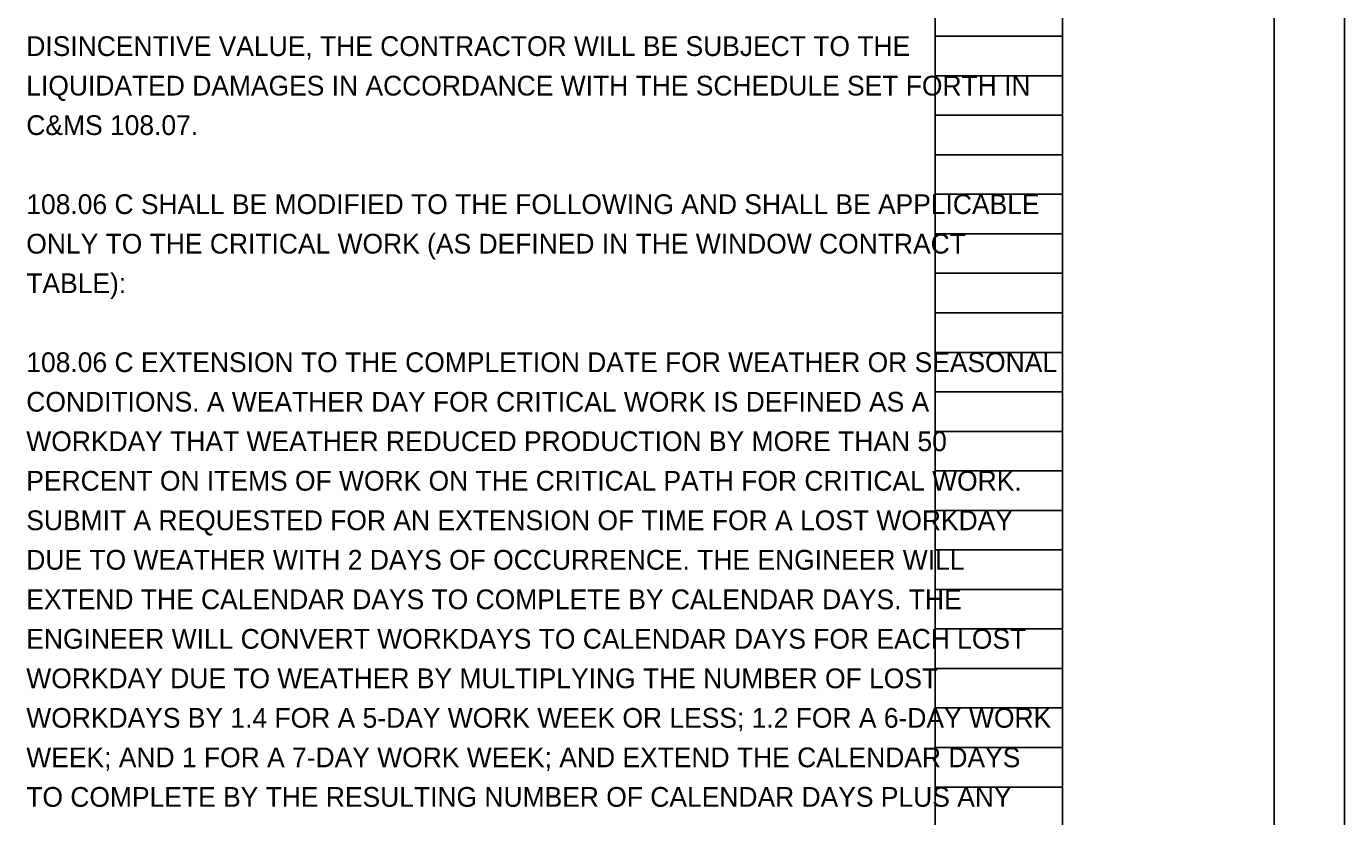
# Model space of a CAD drawing. Extents: x 0 to 84.3, y -13.4 to 22.
# Drawn here: x 24.66 to 34, y 5.53 to 11.13 of the extents above; entities that cross this region are included whole.
import ezdxf

# ---------------------------------------------------------------- set-up
doc = ezdxf.new("R2010")
doc.units = 0
for name, color, linetype in [('SH_Border', 7, 'Continuous'), ('SH_Cut_Line', 7, 'Continuous'), ('SH_Data', 7, 'Continuous'), ('SH_Text', 7, 'Continuous')]:
    doc.layers.add(name, color=color, linetype=linetype)

msp = doc.modelspace()

# ---------------------------------------------------------------- linework, layer by layer
at = {"layer": 'SH_Border'}
msp.add_line((32, 0.5), (32, 21.5), dxfattribs=at)
msp.add_lwpolyline([(1.5, 21.5), (33.5, 21.5), (33.5, 0.5), (1.5, 0.5)], close=True, dxfattribs=at)
at = {"layer": 'SH_Cut_Line'}
msp.add_lwpolyline([(0, 0), (34, 0), (34, 22), (0, 22)], close=True, dxfattribs=at)
at = {"layer": 'SH_Data'}
for p, q in [((31.1, 0.98), (31.1, 21.14)), ((32, 0.98), (32, 21.14)), ((31.1, 11.06), (32, 11.06)), ((31.1, 10.78), (32, 10.78)), ((31.1, 10.5), (32, 10.5)), ((31.1, 10.22), (32, 10.22)), ((31.1, 9.94), (32, 9.94)), ((31.1, 9.66), (32, 9.66)), ((31.1, 9.38), (32, 9.38)), ((31.1, 9.1), (32, 9.1)), ((31.1, 8.82), (32, 8.82)), ((31.1, 8.54), (32, 8.54)), ((31.1, 8.26), (32, 8.26)), ((31.1, 7.98), (32, 7.98)), ((31.1, 7.7), (32, 7.7)), ((31.1, 7.42), (32, 7.42)), ((31.1, 7.14), (32, 7.14)), ((31.1, 6.86), (32, 6.86)), ((31.1, 6.58), (32, 6.58)), ((31.1, 6.3), (32, 6.3)), ((31.1, 6.02), (32, 6.02)), ((31.1, 5.74), (32, 5.74))]:
    msp.add_line(p, q, dxfattribs=at)

# ---------------------------------------------------------------- texts
at = {"layer": 'SH_Text'}
for s, p in [('DISINCENTIVE VALUE, THE CONTRACTOR WILL BE SUBJECT TO THE ', (24.66, 10.92)), ('LIQUIDATED DAMAGES IN ACCORDANCE WITH THE SCHEDULE SET FORTH IN ', (24.66, 10.64)), ('C&MS 108.07.', (24.66, 10.36)), ('108.06 C SHALL BE MODIFIED TO THE FOLLOWING AND SHALL BE APPLICABLE ', (24.66, 9.8)), ('ONLY TO THE CRITICAL WORK (AS DEFINED IN THE WINDOW CONTRACT ', (24.66, 9.52)), ('TABLE): ', (24.66, 9.24)), ('108.06 C EXTENSION TO THE COMPLETION DATE FOR WEATHER OR SEASONAL ', (24.66, 8.68)), ('CONDITIONS. A WEATHER DAY FOR CRITICAL WORK IS DEFINED AS A ', (24.66, 8.4)), ('WORKDAY THAT WEATHER REDUCED PRODUCTION BY MORE THAN 50 ', (24.66, 8.12)), ('PERCENT ON ITEMS OF WORK ON THE CRITICAL PATH FOR CRITICAL WORK. ', (24.66, 7.84)), ('SUBMIT A REQUESTED FOR AN EXTENSION OF TIME FOR A LOST WORKDAY ', (24.66, 7.56)), ('DUE TO WEATHER WITH 2 DAYS OF OCCURRENCE. THE ENGINEER WILL ', (24.66, 7.28)), ('EXTEND THE CALENDAR DAYS TO COMPLETE BY CALENDAR DAYS. THE ', (24.66, 7)), ('ENGINEER WILL CONVERT WORKDAYS TO CALENDAR DAYS FOR EACH LOST ', (24.66, 6.72)), ('WORKDAY DUE TO WEATHER BY MULTIPLYING THE NUMBER OF LOST ', (24.66, 6.44)), ('WORKDAYS BY 1.4 FOR A 5-DAY WORK WEEK OR LESS; 1.2 FOR A 6-DAY WORK ', (24.66, 6.16)), ('WEEK; AND 1 FOR A 7-DAY WORK WEEK; AND EXTEND THE CALENDAR DAYS ', (24.66, 5.88)), ('TO COMPLETE BY THE RESULTING NUMBER OF CALENDAR DAYS PLUS ANY ', (24.66, 5.6))]:
    msp.add_text(s, height=0.14, dxfattribs=at).set_placement(p)

doc.saveas('drawing.dxf')
